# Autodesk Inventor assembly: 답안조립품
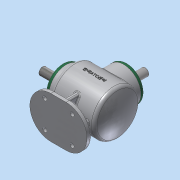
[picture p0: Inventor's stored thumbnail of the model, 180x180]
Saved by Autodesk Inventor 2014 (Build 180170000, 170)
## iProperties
Created: 2023-01
Part Number: 답안조립품
Document SubType Name: Assembly
Designer: dg
Author: dg
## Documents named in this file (14)
- C:\Users\dg\Desktop\730106V1015\답안조립품.iam
- C:\Users\dg\Desktop\730106V1015\M4.ipt
- C:\Users\dg\Desktop\730106V1015\메인 베벨기어.ipt
- C:\Users\dg\Desktop\730106V1015\메인 축.ipt
- 메인 축.ipt
- C:\Users\dg\Desktop\730106V1015\베어링 6203.ipt
- C:\Users\dg\Desktop\730106V1015\본체.ipt
- C:\Users\dg\Desktop\730106V1015\서브 베벨기어.ipt
- C:\Users\dg\Desktop\730106V1015\서브 축.ipt
- 서브 축.ipt
- C:\Users\dg\Desktop\730106V1015\오일실 17 32 8.ipt
- C:\Users\dg\Desktop\730106V1015\커버.ipt
- C:\Users\dg\Desktop\730106V1015\키 4x4.ipt
- C:\Users\dg\Desktop\730106V1015\키 5x5.ipt
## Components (8 placed, 1 different names)
1. M4:1
2. M4:3
3. M4:4
4. M4:5
5. M4:2
6. M4:6
7. M4:7
8. M4:8
